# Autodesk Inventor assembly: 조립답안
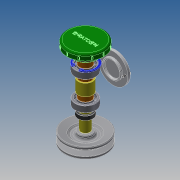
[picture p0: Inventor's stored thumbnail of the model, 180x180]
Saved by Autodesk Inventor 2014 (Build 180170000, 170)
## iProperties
Created: 2017-10
Part Number: 조립답안
Document SubType Name: Assembly
Designer: kb543-05
Author: kb543-05
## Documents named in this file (20)
- C:\Users\kb543-05\Desktop\471007V1001\조립답안.iam
- C:\Users\kb543-05\Desktop\471007V1001\본체.ipt
- C:\Users\kb543-05\Desktop\471007V1001\V-벨트풀리.ipt
- C:\Users\kb543-05\Desktop\471007V1001\너트 M10.ipt
- C:\Users\kb543-05\Desktop\471007V1001\멈춤링 15 x 1.ipt
- C:\Users\kb543-05\Desktop\471007V1001\멈춤링 35x1.6.ipt
- C:\Users\kb543-05\Desktop\471007V1001\베어링 15 x 35 x 11.ipt
- C:\Users\kb543-05\Desktop\471007V1001\볼트 M4 x 10.ipt
- C:\Users\kb543-05\Desktop\471007V1001\부시1.ipt
- C:\Users\kb543-05\Desktop\471007V1001\부시2.ipt
- C:\Users\kb543-05\Desktop\471007V1001\사이드 커버.ipt
- 사이드 커버.ipt
- C:\Users\kb543-05\Desktop\471007V1001\십자볼트 M3 x 10.ipt
- C:\Users\kb543-05\Desktop\471007V1001\오일 실 15 25 7.ipt
- C:\Users\kb543-05\Desktop\471007V1001\와셔 3x6.ipt
- C:\Users\kb543-05\Desktop\471007V1001\와셔 4x16.ipt
- C:\Users\kb543-05\Desktop\471007V1001\와셔 10x21.ipt
- C:\Users\kb543-05\Desktop\471007V1001\축.ipt
- C:\Users\kb543-05\Desktop\471007V1001\키 4 x 4 x 18.ipt
- C:\Users\kb543-05\Desktop\471007V1001\탑 커버.ipt
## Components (2 placed, 2 different names)
1. V-벨트풀리:1 — 각도:2
2. ISO 4017 M4 x 10:1
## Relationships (1: Angle 1)
- 각도:2 [Angle]: V-벨트풀리:1
